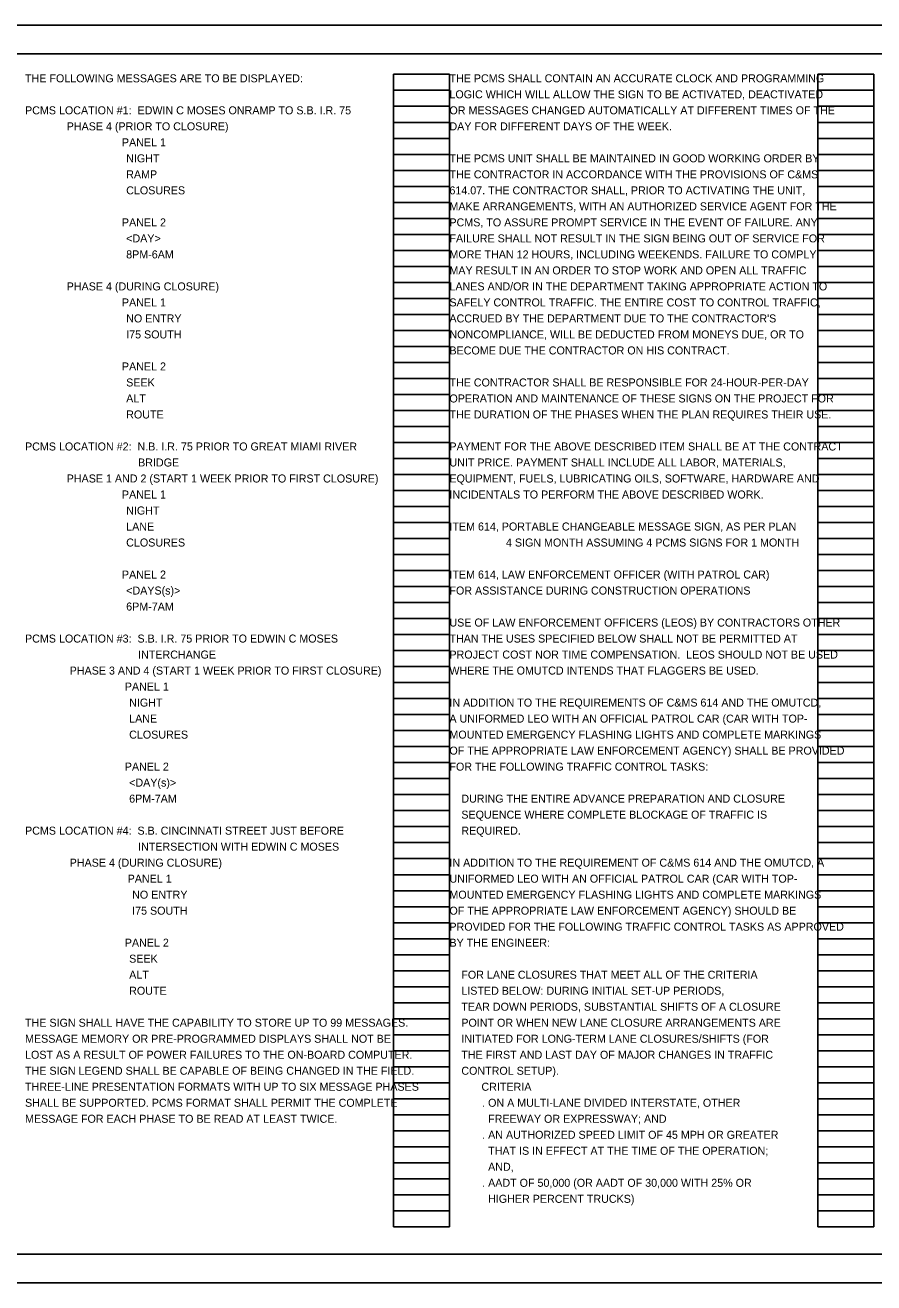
# Model space of a CAD drawing. Extents: x 0 to 43.1, y 0 to 22.
# Drawn here: x 9.82 to 24.66, y 0 to 22 of the extents above; entities that cross this region are included whole.
import ezdxf

# ---------------------------------------------------------------- set-up
doc = ezdxf.new("R2010")
doc.units = 0
for name, color, linetype in [('SC_Scratch1', 7, 'Continuous'), ('SH_Border', 7, 'Continuous'), ('SH_Cut_Line', 7, 'Continuous'), ('SH_Text', 7, 'Continuous')]:
    doc.layers.add(name, color=color, linetype=linetype)

msp = doc.modelspace()

# ---------------------------------------------------------------- linework, layer by layer
at = {"layer": 'SC_Scratch1'}
for p, q in [((16.26, 0.98), (16.26, 21.14)), ((16.26, 21.14), (17.24, 21.14)), ((17.24, 0.98), (17.24, 21.14)), ((23.68, 0.98), (23.68, 21.14)), ((23.68, 21.14), (24.66, 21.14)), ((24.66, 0.98), (24.66, 21.14)), ((16.26, 20.86), (17.24, 20.86)), ((23.68, 20.86), (24.66, 20.86)), ((16.26, 20.58), (17.24, 20.58)), ((23.68, 20.58), (24.66, 20.58)), ((16.26, 20.3), (17.24, 20.3)), ((23.68, 20.3), (24.66, 20.3)), ((16.26, 20.02), (17.24, 20.02)), ((23.68, 20.02), (24.66, 20.02)), ((16.26, 19.74), (17.24, 19.74)), ((23.68, 19.74), (24.66, 19.74)), ((16.26, 19.46), (17.24, 19.46)), ((23.68, 19.46), (24.66, 19.46)), ((16.26, 19.18), (17.24, 19.18)), ((23.68, 19.18), (24.66, 19.18)), ((16.26, 18.9), (17.24, 18.9)), ((23.68, 18.9), (24.66, 18.9)), ((16.26, 18.62), (17.24, 18.62)), ((23.68, 18.62), (24.66, 18.62)), ((16.26, 18.34), (17.24, 18.34)), ((23.68, 18.34), (24.66, 18.34)), ((16.26, 18.06), (17.24, 18.06)), ((23.68, 18.06), (24.66, 18.06)), ((16.26, 17.78), (17.24, 17.78)), ((23.68, 17.78), (24.66, 17.78)), ((16.26, 17.5), (17.24, 17.5)), ((23.68, 17.5), (24.66, 17.5)), ((16.26, 17.22), (17.24, 17.22)), ((23.68, 17.22), (24.66, 17.22)), ((16.26, 16.94), (17.24, 16.94)), ((23.68, 16.94), (24.66, 16.94)), ((16.26, 16.66), (17.24, 16.66)), ((23.68, 16.66), (24.66, 16.66)), ((16.26, 16.38), (17.24, 16.38)), ((23.68, 16.38), (24.66, 16.38)), ((16.26, 16.1), (17.24, 16.1)), ((23.68, 16.1), (24.66, 16.1)), ((16.26, 15.82), (17.24, 15.82)), ((23.68, 15.82), (24.66, 15.82)), ((16.26, 15.54), (17.24, 15.54)), ((23.68, 15.54), (24.66, 15.54)), ((16.26, 15.26), (17.24, 15.26)), ((23.68, 15.26), (24.66, 15.26)), ((16.26, 14.98), (17.24, 14.98)), ((23.68, 14.98), (24.66, 14.98)), ((16.26, 14.7), (17.24, 14.7)), ((23.68, 14.7), (24.66, 14.7)), ((16.26, 14.42), (17.24, 14.42)), ((23.68, 14.42), (24.66, 14.42)), ((16.26, 14.14), (17.24, 14.14)), ((23.68, 14.14), (24.66, 14.14)), ((16.26, 13.86), (17.24, 13.86)), ((23.68, 13.86), (24.66, 13.86)), ((16.26, 13.58), (17.24, 13.58)), ((23.68, 13.58), (24.66, 13.58)), ((16.26, 13.3), (17.24, 13.3)), ((23.68, 13.3), (24.66, 13.3)), ((16.26, 13.02), (17.24, 13.02)), ((23.68, 13.02), (24.66, 13.02)), ((16.26, 12.74), (17.24, 12.74)), ((23.68, 12.74), (24.66, 12.74)), ((16.26, 12.46), (17.24, 12.46)), ((23.68, 12.46), (24.66, 12.46)), ((16.26, 12.18), (17.24, 12.18)), ((23.68, 12.18), (24.66, 12.18)), ((16.26, 11.9), (17.24, 11.9)), ((23.68, 11.9), (24.66, 11.9)), ((16.26, 11.62), (17.24, 11.62)), ((23.68, 11.62), (24.66, 11.62)), ((16.26, 11.34), (17.24, 11.34)), ((23.68, 11.34), (24.66, 11.34)), ((16.26, 11.06), (17.24, 11.06)), ((23.68, 11.06), (24.66, 11.06)), ((16.26, 10.78), (17.24, 10.78)), ((23.68, 10.78), (24.66, 10.78)), ((16.26, 10.5), (17.24, 10.5)), ((23.68, 10.5), (24.66, 10.5)), ((16.26, 10.22), (17.24, 10.22)), ((23.68, 10.22), (24.66, 10.22)), ((16.26, 9.94), (17.24, 9.94)), ((23.68, 9.94), (24.66, 9.94)), ((16.26, 9.66), (17.24, 9.66)), ((23.68, 9.66), (24.66, 9.66)), ((16.26, 9.38), (17.24, 9.38)), ((23.68, 9.38), (24.66, 9.38)), ((16.26, 9.1), (17.24, 9.1)), ((23.68, 9.1), (24.66, 9.1)), ((16.26, 8.82), (17.24, 8.82)), ((23.68, 8.82), (24.66, 8.82)), ((16.26, 8.54), (17.24, 8.54)), ((23.68, 8.54), (24.66, 8.54)), ((16.26, 8.26), (17.24, 8.26)), ((23.68, 8.26), (24.66, 8.26)), ((16.26, 7.98), (17.24, 7.98)), ((23.68, 7.98), (24.66, 7.98)), ((16.26, 7.7), (17.24, 7.7)), ((23.68, 7.7), (24.66, 7.7)), ((16.26, 7.42), (17.24, 7.42)), ((23.68, 7.42), (24.66, 7.42)), ((16.26, 7.14), (17.24, 7.14)), ((23.68, 7.14), (24.66, 7.14)), ((16.26, 6.86), (17.24, 6.86)), ((23.68, 6.86), (24.66, 6.86)), ((16.26, 6.58), (17.24, 6.58)), ((23.68, 6.58), (24.66, 6.58)), ((16.26, 6.3), (17.24, 6.3)), ((23.68, 6.3), (24.66, 6.3)), ((16.26, 6.02), (17.24, 6.02)), ((23.68, 6.02), (24.66, 6.02)), ((16.26, 5.74), (17.24, 5.74)), ((23.68, 5.74), (24.66, 5.74)), ((16.26, 5.46), (17.24, 5.46)), ((23.68, 5.46), (24.66, 5.46)), ((16.26, 5.18), (17.24, 5.18)), ((23.68, 5.18), (24.66, 5.18)), ((16.26, 4.9), (17.24, 4.9)), ((23.68, 4.9), (24.66, 4.9)), ((16.26, 4.62), (17.24, 4.62)), ((23.68, 4.62), (24.66, 4.62)), ((16.26, 4.34), (17.24, 4.34)), ((23.68, 4.34), (24.66, 4.34)), ((16.26, 4.06), (17.24, 4.06)), ((23.68, 4.06), (24.66, 4.06)), ((16.26, 3.78), (17.24, 3.78)), ((23.68, 3.78), (24.66, 3.78)), ((16.26, 3.5), (17.24, 3.5)), ((23.68, 3.5), (24.66, 3.5)), ((16.26, 3.22), (17.24, 3.22)), ((23.68, 3.22), (24.66, 3.22)), ((16.26, 2.94), (17.24, 2.94)), ((23.68, 2.94), (24.66, 2.94)), ((16.26, 2.66), (17.24, 2.66)), ((23.68, 2.66), (24.66, 2.66)), ((16.26, 2.38), (17.24, 2.38)), ((23.68, 2.38), (24.66, 2.38)), ((16.26, 2.1), (17.24, 2.1)), ((23.68, 2.1), (24.66, 2.1)), ((16.26, 1.82), (17.24, 1.82)), ((23.68, 1.82), (24.66, 1.82)), ((16.26, 1.54), (17.24, 1.54)), ((23.68, 1.54), (24.66, 1.54)), ((16.26, 1.26), (17.24, 1.26)), ((23.68, 1.26), (24.66, 1.26)), ((16.26, 0.98), (17.24, 0.98)), ((23.68, 0.98), (24.66, 0.98))]:
    msp.add_line(p, q, dxfattribs=at)
at = {"layer": 'SH_Border'}
msp.add_lwpolyline([(1.5, 21.5), (33.5, 21.5), (33.5, 0.5), (1.5, 0.5)], close=True, dxfattribs=at)
at = {"layer": 'SH_Cut_Line'}
msp.add_lwpolyline([(0, 0), (34, 0), (34, 22), (0, 22)], close=True, dxfattribs=at)

# ---------------------------------------------------------------- texts
at = {"layer": 'SH_Text'}
for s, p in [('THE FOLLOWING MESSAGES ARE TO BE DISPLAYED:', (9.82, 21)), ('THE PCMS SHALL CONTAIN AN ACCURATE CLOCK AND PROGRAMMING ', (17.24, 21)), ('LOGIC WHICH WILL ALLOW THE SIGN TO BE ACTIVATED, DEACTIVATED ', (17.24, 20.72)), ('PCMS LOCATION #1:  EDWIN C MOSES ONRAMP TO S.B. I.R. 75', (9.82, 20.44)), ('OR MESSAGES CHANGED AUTOMATICALLY AT DIFFERENT TIMES OF THE ', (17.24, 20.44)), ('              PHASE 4 (PRIOR TO CLOSURE)', (9.82, 20.16)), ('DAY FOR DIFFERENT DAYS OF THE WEEK.', (17.24, 20.16)), ('PANEL 1', (11.514, 19.88)), ('                                  NIGHT', (9.82, 19.6)), ('THE PCMS UNIT SHALL BE MAINTAINED IN GOOD WORKING ORDER BY ', (17.24, 19.6)), ('                                  RAMP', (9.82, 19.32)), ('THE CONTRACTOR IN ACCORDANCE WITH THE PROVISIONS OF C&MS ', (17.24, 19.32)), ('                                  CLOSURES', (9.82, 19.04)), ('614.07. THE CONTRACTOR SHALL, PRIOR TO ACTIVATING THE UNIT, ', (17.24, 19.04)), ('MAKE ARRANGEMENTS, WITH AN AUTHORIZED SERVICE AGENT FOR THE ', (17.24, 18.76)), ('PANEL 2', (11.514, 18.48)), ('PCMS, TO ASSURE PROMPT SERVICE IN THE EVENT OF FAILURE. ANY ', (17.24, 18.48)), ('                                  <DAY>', (9.82, 18.2)), ('FAILURE SHALL NOT RESULT IN THE SIGN BEING OUT OF SERVICE FOR ', (17.24, 18.2)), ('                                  8PM-6AM', (9.82, 17.92)), ('MORE THAN 12 HOURS, INCLUDING WEEKENDS. FAILURE TO COMPLY ', (17.24, 17.92)), ('MAY RESULT IN AN ORDER TO STOP WORK AND OPEN ALL TRAFFIC ', (17.24, 17.64)), ('              PHASE 4 (DURING CLOSURE)', (9.82, 17.36)), ('LANES AND/OR IN THE DEPARTMENT TAKING APPROPRIATE ACTION TO ', (17.24, 17.36)), ('PANEL 1', (11.514, 17.08)), ('SAFELY CONTROL TRAFFIC. THE ENTIRE COST TO CONTROL TRAFFIC, ', (17.24, 17.08)), ('                                  NO ENTRY', (9.82, 16.8)), ("ACCRUED BY THE DEPARTMENT DUE TO THE CONTRACTOR'S ", (17.24, 16.8)), ('                                  I75 SOUTH', (9.82, 16.52)), ('NONCOMPLIANCE, WILL BE DEDUCTED FROM MONEYS DUE, OR TO ', (17.24, 16.52)), ('BECOME DUE THE CONTRACTOR ON HIS CONTRACT.', (17.24, 16.24)), ('PANEL 2', (11.514, 15.96)), ('                                  SEEK', (9.82, 15.68)), ('THE CONTRACTOR SHALL BE RESPONSIBLE FOR 24-HOUR-PER-DAY ', (17.24, 15.68)), ('                                  ALT', (9.82, 15.4)), ('OPERATION AND MAINTENANCE OF THESE SIGNS ON THE PROJECT FOR ', (17.24, 15.4)), ('                                  ROUTE', (9.82, 15.12)), ('THE DURATION OF THE PHASES WHEN THE PLAN REQUIRES THEIR USE.', (17.24, 15.12)), ('PCMS LOCATION #2:  N.B. I.R. 75 PRIOR TO GREAT MIAMI RIVER', (9.82, 14.56)), ('PAYMENT FOR THE ABOVE DESCRIBED ITEM SHALL BE AT THE CONTRACT ', (17.24, 14.56)), ('                                      BRIDGE', (9.82, 14.28)), ('UNIT PRICE. PAYMENT SHALL INCLUDE ALL LABOR, MATERIALS, ', (17.24, 14.28)), ('              PHASE 1 AND 2 (START 1 WEEK PRIOR TO FIRST CLOSURE)', (9.82, 14)), ('EQUIPMENT, FUELS, LUBRICATING OILS, SOFTWARE, HARDWARE AND ', (17.24, 14)), ('PANEL 1', (11.514, 13.72)), ('INCIDENTALS TO PERFORM THE ABOVE DESCRIBED WORK.', (17.24, 13.72)), ('                                  NIGHT', (9.82, 13.44)), ('                                  LANE ', (9.82, 13.16)), ('ITEM 614, PORTABLE CHANGEABLE MESSAGE SIGN, AS PER PLAN', (17.24, 13.16)), ('                                  CLOSURES', (9.82, 12.88)), ('                   4 SIGN MONTH ASSUMING 4 PCMS SIGNS FOR 1 MONTH', (17.24, 12.88)), ('PANEL 2', (11.514, 12.32)), ('ITEM 614, LAW ENFORCEMENT OFFICER (WITH PATROL CAR)', (17.24, 12.32)), ('                                  <DAYS(s)>', (9.82, 12.04)), ('FOR ASSISTANCE DURING CONSTRUCTION OPERATIONS', (17.24, 12.04)), ('                                  6PM-7AM', (9.82, 11.76)), ('USE OF LAW ENFORCEMENT OFFICERS (LEOS) BY CONTRACTORS OTHER ', (17.24, 11.48)), ('PCMS LOCATION #3:  S.B. I.R. 75 PRIOR TO EDWIN C MOSES', (9.82, 11.2)), ('THAN THE USES SPECIFIED BELOW SHALL NOT BE PERMITTED AT ', (17.24, 11.2)), ('                                      INTERCHANGE', (9.82, 10.92)), ('PROJECT COST NOR TIME COMPENSATION.  LEOS SHOULD NOT BE USED ', (17.24, 10.92)), ('               PHASE 3 AND 4 (START 1 WEEK PRIOR TO FIRST CLOSURE)', (9.82, 10.64)), ('WHERE THE OMUTCD INTENDS THAT FLAGGERS BE USED.', (17.24, 10.64)), ('PANEL 1', (11.564, 10.36)), ('                                   NIGHT', (9.82, 10.08)), ('IN ADDITION TO THE REQUIREMENTS OF C&MS 614 AND THE OMUTCD, ', (17.24, 10.08)), ('                                   LANE', (9.82, 9.8)), ('A UNIFORMED LEO WITH AN OFFICIAL PATROL CAR (CAR WITH TOP-', (17.24, 9.8)), ('                                   CLOSURES', (9.82, 9.52)), ('MOUNTED EMERGENCY FLASHING LIGHTS AND COMPLETE MARKINGS ', (17.24, 9.52)), ('OF THE APPROPRIATE LAW ENFORCEMENT AGENCY) SHALL BE PROVIDED ', (17.24, 9.24)), ('PANEL 2', (11.564, 8.96)), ('FOR THE FOLLOWING TRAFFIC CONTROL TASKS:', (17.24, 8.96)), ('                                   <DAY(s)>', (9.82, 8.68)), ('                                   6PM-7AM', (9.82, 8.4)), ('    DURING THE ENTIRE ADVANCE PREPARATION AND CLOSURE', (17.24, 8.4)), ('    SEQUENCE WHERE COMPLETE BLOCKAGE OF TRAFFIC IS', (17.24, 8.12)), ('PCMS LOCATION #4:  S.B. CINCINNATI STREET JUST BEFORE', (9.82, 7.84)), ('    REQUIRED.', (17.24, 7.84)), ('                                      INTERSECTION WITH EDWIN C MOSES', (9.82, 7.56)), ('               PHASE 4 (DURING CLOSURE)', (9.82, 7.28)), ('IN ADDITION TO THE REQUIREMENT OF C&MS 614 AND THE OMUTCD, A ', (17.24, 7.28)), ('PANEL 1', (11.614, 7)), ('UNIFORMED LEO WITH AN OFFICIAL PATROL CAR (CAR WITH TOP-', (17.24, 7)), ('                                    NO ENTRY', (9.82, 6.72)), ('MOUNTED EMERGENCY FLASHING LIGHTS AND COMPLETE MARKINGS ', (17.24, 6.72)), ('                                    I75 SOUTH', (9.82, 6.44)), ('OF THE APPROPRIATE LAW ENFORCEMENT AGENCY) SHOULD BE ', (17.24, 6.44)), ('PROVIDED FOR THE FOLLOWING TRAFFIC CONTROL TASKS AS APPROVED ', (17.24, 6.16)), ('PANEL 2', (11.564, 5.88)), ('BY THE ENGINEER:', (17.24, 5.88)), ('                                   SEEK', (9.82, 5.6)), ('                                   ALT', (9.82, 5.32)), ('    FOR LANE CLOSURES THAT MEET ALL OF THE CRITERIA ', (17.24, 5.32)), ('                                   ROUTE', (9.82, 5.04)), ('    LISTED BELOW: DURING INITIAL SET-UP PERIODS,', (17.24, 5.04)), ('    TEAR DOWN PERIODS, SUBSTANTIAL SHIFTS OF A CLOSURE', (17.24, 4.76)), ('THE SIGN SHALL HAVE THE CAPABILITY TO STORE UP TO 99 MESSAGES.  ', (9.82, 4.48)), ('    POINT OR WHEN NEW LANE CLOSURE ARRANGEMENTS ARE', (17.24, 4.48)), ('MESSAGE MEMORY OR PRE-PROGRAMMED DISPLAYS SHALL NOT BE ', (9.82, 4.2)), ('    INITIATED FOR LONG-TERM LANE CLOSURES/SHIFTS (FOR', (17.24, 4.2)), ('LOST AS A RESULT OF POWER FAILURES TO THE ON-BOARD COMPUTER. ', (9.82, 3.92)), ('    THE FIRST AND LAST DAY OF MAJOR CHANGES IN TRAFFIC', (17.24, 3.92)), ('THE SIGN LEGEND SHALL BE CAPABLE OF BEING CHANGED IN THE FIELD. ', (9.82, 3.64)), ('    CONTROL SETUP).', (17.24, 3.64)), ('THREE-LINE PRESENTATION FORMATS WITH UP TO SIX MESSAGE PHASES ', (9.82, 3.36)), ('CRITERIA', (17.8, 3.36)), ('SHALL BE SUPPORTED. PCMS FORMAT SHALL PERMIT THE COMPLETE ', (9.82, 3.08)), ('           . ON A MULTI-LANE DIVIDED INTERSTATE, OTHER', (17.24, 3.08)), ('MESSAGE FOR EACH PHASE TO BE READ AT LEAST TWICE.', (9.82, 2.8)), ('             FREEWAY OR EXPRESSWAY; AND', (17.24, 2.8)), ('           . AN AUTHORIZED SPEED LIMIT OF 45 MPH OR GREATER', (17.24, 2.52)), ('             THAT IS IN EFFECT AT THE TIME OF THE OPERATION;', (17.24, 2.24)), ('             AND,', (17.24, 1.96)), ('           . AADT OF 50,000 (OR AADT OF 30,000 WITH 25% OR', (17.24, 1.68)), ('             HIGHER PERCENT TRUCKS)', (17.24, 1.4))]:
    msp.add_text(s, height=0.14, dxfattribs=at).set_placement(p)

doc.saveas('drawing.dxf')
